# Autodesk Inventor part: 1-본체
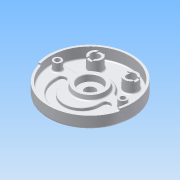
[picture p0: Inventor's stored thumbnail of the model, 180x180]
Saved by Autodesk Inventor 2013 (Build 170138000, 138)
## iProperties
Created: 2015-06
Part Number: 1-본체
Material: 알루미늄 6061
Document SubType Name: Modeling
Designer: Administrator
Mass: 959.322 g
Surface Area: 1038.99 cm^2
Volume: 398.503 cm^3
Density: 2.40731 g/cm^3
Author: Administrator
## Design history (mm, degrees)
sketch "스케치1"
  geometry: C1 r 95 at (0, 0); 1 further point
  constraints: 1 centre point, 1 coincident
  dimensions: "d0" = 190 diameter of C1
extrude "돌출1" new body sketch "스케치1" distance "d2" = 32; taper "d3" = 0 deg
sketch "스케치2"
  geometry: C1 r 95 at (0, 0) reference; C2 r 90 at (0, 0)
  constraints: 1 centre point, 1 coincident
  dimensions: "d4" = 180 diameter of C2
extrude "돌출2" cut sketch "스케치2" distance "d6" = 25; taper "d7" = 0 deg
sketch "스케치3"
  geometry: L1 (-95, 0)-(95, 0); L2 (-86.318, -25.48)-(-91.32, -26.184); L3 (86.769, -23.898)-(91.76, -24.6); A1 r 90 centre (0, 0) between (-86.318, -25.48) and (86.769, -23.898) reference; A2 r 95 centre (0, 0) between (-95, 0) and (95, 0) reference
  constraints: 6 end point, 6 point on circle, 1 horizontal
  dimensions: "d8" = 8 deg angle of L3 L1; "d11" = 5.00273 horizontal distance of L2.start L2.end; "d12" = 4.9907 horizontal distance of L3.start L3.end; "d25" = 8 deg angle of L2 L1
extrude "돌출3" cut sketch "스케치3" distance "d13" = 5; taper "d14" = 0 deg
sketch "스케치4"
  geometry: L1 (-90, 0)-(90, 0); L2 (-90, -19)-(90, -19); L3 (-90, 16)-(-38.833, 16); L4 (38.833, 16)-(90, 16); L5 (-90, -14)-(90, -14); L6 (-59, -19)-(-59, -14); L7 (-41, -19)-(-41, -14); L8 (59, -19)-(59, -14); L9 (41, -19)-(41, -14); A1 r 90 centre (0, 0) between (90, 0) and (-90, 0) reference; A2 r 41 centre (0, -19) between (-41, -19) and (41, -19); A3 r 59 centre (0, -19) between (-59, -19) and (59, -19); A4 r 42 centre (0, 0) between (38.833, 16) and (-38.833, 16); A5 r 9 centre (50, -14) between (59, -14) and (41, -14); A6 r 9 centre (-50, -14) between (-41, -14) and (-59, -14); A7 r 90 centre (0, 0) between (-88.566, 16) and (88.566, 16); 2 further points
  constraints: 18 end point, 14 point on circle, 8 point on line, 7 parallel, 6 centre point, 5 tangent, 4 coincident, 3 midpoint, 1 collinear, 1 horizontal, 1 vertical, 1 vertical alignment
  dimensions: "d18" = 19 distance between parallel lines of L2 L1; "d21" = 42 radius of A4; "d22" = 16 distance between parallel lines of L1 L3; "d23" = 41 radius of A2; "d24" = 59 radius of A3; "d26" = 5 distance between parallel lines of L2 L5; "d30" = 18 diameter of A5; "d31" = 9 radius of A6; "d32" = 180 diameter of A7
extrude "돌출4" join sketch "스케치4" distance "d33" = 7; taper "d34" = 0 deg
sketch "스케치5"
  geometry: C1 r 15 at (-40, 52); C2 r 15 at (40, 52); A1 r 42 centre (0, 0) between (38.833, 16) and (-38.833, 16) reference
  constraints: 2 centre point, 1 equal radius, 1 horizontal alignment
  dimensions: "d35" = 52 vertical distance of A1.centre C2.centre; "d36" = 40 horizontal distance of C2.centre A1.centre; "d37" = 80 distance of C1.centre C2.centre; "d38" = 30 diameter of C1
extrude "돌출5" join sketch "스케치5" stored distance "d39" = 14; taper "d40" = 0 deg
hole "구멍1" diameter "d47" = 20; stored, may be unused: countersink angle "d51" = 90 deg, drill point angle "d53" = 118 deg; dims "d45" = 10, "d46" = 10, "d48" = 6, "d49" = 4, "d50" = 2, "d52" = 8
hole "구멍2" diameter "d56" = 20; stored, may be unused: countersink angle "d60" = 90 deg, drill point angle "d62" = 118 deg; dims "d54" = 10, "d55" = 10, "d57" = 6, "d58" = 4, "d59" = 2, "d61" = 8
sketch "스케치7"
  geometry: L1 (-6, -13.748)-(-6, 13.748); L2 (6, 13.748)-(6, -13.748); L3 (66.252, 6)-(93.748, 6); L4 (66.252, -6)-(93.748, -6); C1 r 10 at (0, 0) reference; C2 r 10 at (80, 0) reference; A1 r 15 centre (0, 0) between (6, -13.748) and (-6, -13.748) reference; A2 r 15 centre (80, 0) between (93.748, 6) and (93.748, -6) reference; 1 further point
  constraints: 8 end point, 8 point on circle, 2 parallel, 1 perpendicular, 1 vertical
  dimensions: "d63" = 6 distance from line of L1 C1.centre; "d64" = 12 distance between parallel lines of L2 L1; "d65" = 6 distance from line of C2.centre L3; "d66" = 12 distance between parallel lines of L4 L3
extrude "돌출6" cut sketch "스케치7" distance "d67" = 3; taper "d68" = 0 deg
sketch "스케치8"
  geometry: C1 r 9 at (-74, 0); C2 r 35 at (0, 0); C3 r 9 at (74, 0); A1 r 42 centre (0, 0) between (38.833, 16) and (-38.833, 16) reference; A2 r 90 centre (0, 0) between (-88.566, 16) and (88.566, 16) reference
  constraints: 3 centre point, 2 horizontal alignment, 1 coincident, 1 equal radius
  dimensions: "d69" = 148 distance of C3.centre C1.centre; "d71" = 74 distance of A1.centre C1.centre; "d72" = 18 diameter of C1; "d73" = 70 diameter of C2
extrude "돌출7" join sketch "스케치8" distance "d74" = 10; taper "d75" = -10 deg
extrude "돌출8" join sketch "스케치8" stored distance "d76" = 10; taper "d77" = 0 deg
hole "구멍3" diameter "d80" = 23; stored, may be unused: countersink angle "d84" = 90 deg, drill point angle "d86" = 118 deg; dims "d78" = 10, "d79" = 10, "d81" = 6, "d82" = 50, "d83" = 15, "d85" = 8
sketch "스케치9"
  geometry: C1 r 95 at (0, 0) reference; C2 r 26 at (0, 0)
  constraints: 1 centre point, 1 coincident
  dimensions: "d87" = 52 diameter of C2
extrude "돌출9" join sketch "스케치9" distance "d89" = 12; taper "d90" = -15 deg
hole "구멍4" diameter "d93" = 23; stored, may be unused: countersink angle "d97" = 90 deg, drill point angle "d99" = 118 deg; dims "d91" = 10, "d92" = 10, "d94" = 6, "d95" = 50, "d96" = 15, "d98" = 8
sketch "스케치10"
  geometry: C1 r 9 at (-74, 0) reference; C2 r 9 at (74, 0) reference; 2 further points
  constraints: 2 coincident
hole "구멍5" sketch "스케치10" at (-74, 0), (74, 0) diameter "d100" = 11; stored, may be unused: countersink angle "d104" = 90 deg, drill point angle "d106" = 118 deg; dims "d101" = 6, "d102" = 18, "d103" = 11, "d105" = 8
fillet "모깎기1" dims "d107" = 10
fillet "모깎기2" dims "d108" = 3
fillet "모깎기3" dims "d109" = 3, "d125" = 1
chamfer "모따기1" distance "d110" = 1; stored, may be unused: second distance "d111" = 2, angle "d112" = 45 deg
fillet "모깎기4" dims "d113" = 3
fillet "모깎기5" dims "d114" = 3, "d123" = 5
sketch "스케치11"
  geometry: C1 r 28.302 at (0, 0) reference; C2 r 68 at (0, 0)
  constraints: 1 centre point, 1 coincident, 1 other
  dimensions: "d115" = 136 diameter of C2
feature "엠보싱1" sketch "스케치11" dims "d117" = 0.5, "d118" = 0
chamfer "모따기2" distance "d119" = 1; stored, may be unused: second distance "d120" = 2, angle "d121" = 45 deg
fillet "모깎기6" dims "d122" = 3
fillet "모깎기7" dims "d124" = 0.3
node "솔리드1"
node "투영된 루프2"
other parameters: "d15" = 84, "d17" = 16, "d19" = 59, "d20" = 41, "d29" = 18
